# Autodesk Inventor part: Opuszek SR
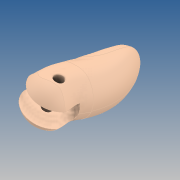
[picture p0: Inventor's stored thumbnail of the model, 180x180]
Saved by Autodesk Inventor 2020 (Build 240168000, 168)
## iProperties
Created: 2019-10
Part Number: Opuszek SR
Material: GFRP
Document SubType Name: Modeling
Designer: yello
Density: 1.75 g/cm^3
Appearance: Default
Author: yello
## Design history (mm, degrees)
feature "Opuszek SR"
sketch "Sketch1"
  geometry: C1 r 2 at (0, 0); 1 further point
  constraints: 1 centre point
  dimensions: "d0" = 4 diameter of C1
extrude "Extrusion1" cut sketch "Sketch1" stored distance "d1" = 100; taper "d2" = 0 deg
body "Solid1"
